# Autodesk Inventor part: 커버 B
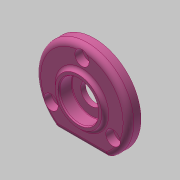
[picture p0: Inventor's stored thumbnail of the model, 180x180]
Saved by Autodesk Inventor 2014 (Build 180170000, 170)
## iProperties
Created: 2020-04
Part Number: 커버 B
Material: 알루미늄 6061
Document SubType Name: Modeling
Designer: mduedu
Density: 1 g/cm^3
Appearance: 분홍색
Author: mduedu
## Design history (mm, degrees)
sketch "스케치1"
  geometry: C1 r 26 at (0, 0); 1 further point
  constraints: 1 centre point, 1 coincident
  dimensions: "d0" = 52 diameter of C1
extrude "돌출1" new body sketch "스케치1" distance "d1" = 7; taper "d2" = 0 deg
sketch "스케치2"
  geometry: L1 (-14.62, -21.5)-(14.62, -21.5); A1 r 26 centre (0, 0) between (-14.62, -21.5) and (14.62, -21.5) reference; 1 further point
  constraints: 2 end point, 2 point on circle, 1 horizontal
  dimensions: "d3" = 21.5 distance from line of L1 point (0, 0)
extrude "돌출2" cut sketch "스케치2" stored distance "d4" = 7; taper "d5" = 0 deg
sketch "스케치6"
  geometry: C1 r 13 at (0, 0); 1 further point
  constraints: 1 centre point, 1 coincident
  dimensions: "d29" = 26 diameter of C1
extrude "돌출5" join sketch "스케치6" distance "d30" = 2; taper "d31" = 0 deg
fillet "모깎기1" dims "d6" = 3
fillet "모깎기2" dims "d7" = 3
fillet "모깎기4" dims "d33" = 2
sketch "스케치3" dims "d8" = 40
  geometry: 3 further points
  constraints: 2 vertical alignment, 1 coincident, 2 other
hole "구멍1" sketch "스케치3" at (0, 20) diameter "d9" = 4.5; stored, may be unused: countersink angle "d13" = 90 deg, drill point angle "d15" = 118 deg; dims "d10" = 6, "d11" = 8, "d12" = 4.4, "d14" = 8
sketch "스케치4"
  geometry: C1 r 14 at (0, 0); 1 further point
  constraints: 1 centre point, 1 coincident
  dimensions: "d19" = 28 diameter of C1
extrude "돌출3" join sketch "스케치4" distance "d20" = 4; taper "d21" = 0 deg
sketch "스케치5"
  geometry: C1 r 12 at (0, 0); 1 further point
  constraints: 1 centre point, 1 coincident
  dimensions: "d22" = 24 diameter of C1
extrude "돌출4" cut sketch "스케치5" distance "d23" = 3; taper "d24" = 0 deg
fillet "모깎기3" dims "d25" = 3
chamfer "모따기1" distance "d26" = 0.5; stored, may be unused: second distance "d27" = 2, angle "d28" = 45 deg
sketch "스케치7"
  geometry: 2 further points
  constraints: 1 coincident
hole "구멍2" sketch "스케치7" at (0, 0) diameter "d34" = 12; stored, may be unused: countersink angle "d38" = 90 deg, drill point angle "d40" = 118 deg; dims "d35" = 6, "d36" = 22, "d37" = 7.3, "d39" = 8
fillet "모깎기5" dims "d41" = 0.3
chamfer "모따기2" distance "d42" = 0.7; stored, may be unused: second distance "d43" = 2, angle "d44" = 30 deg
node "솔리드1"
pattern_circular "원형 패턴1" dims angle "d17" = 360 deg
node "투영된 루프1"
